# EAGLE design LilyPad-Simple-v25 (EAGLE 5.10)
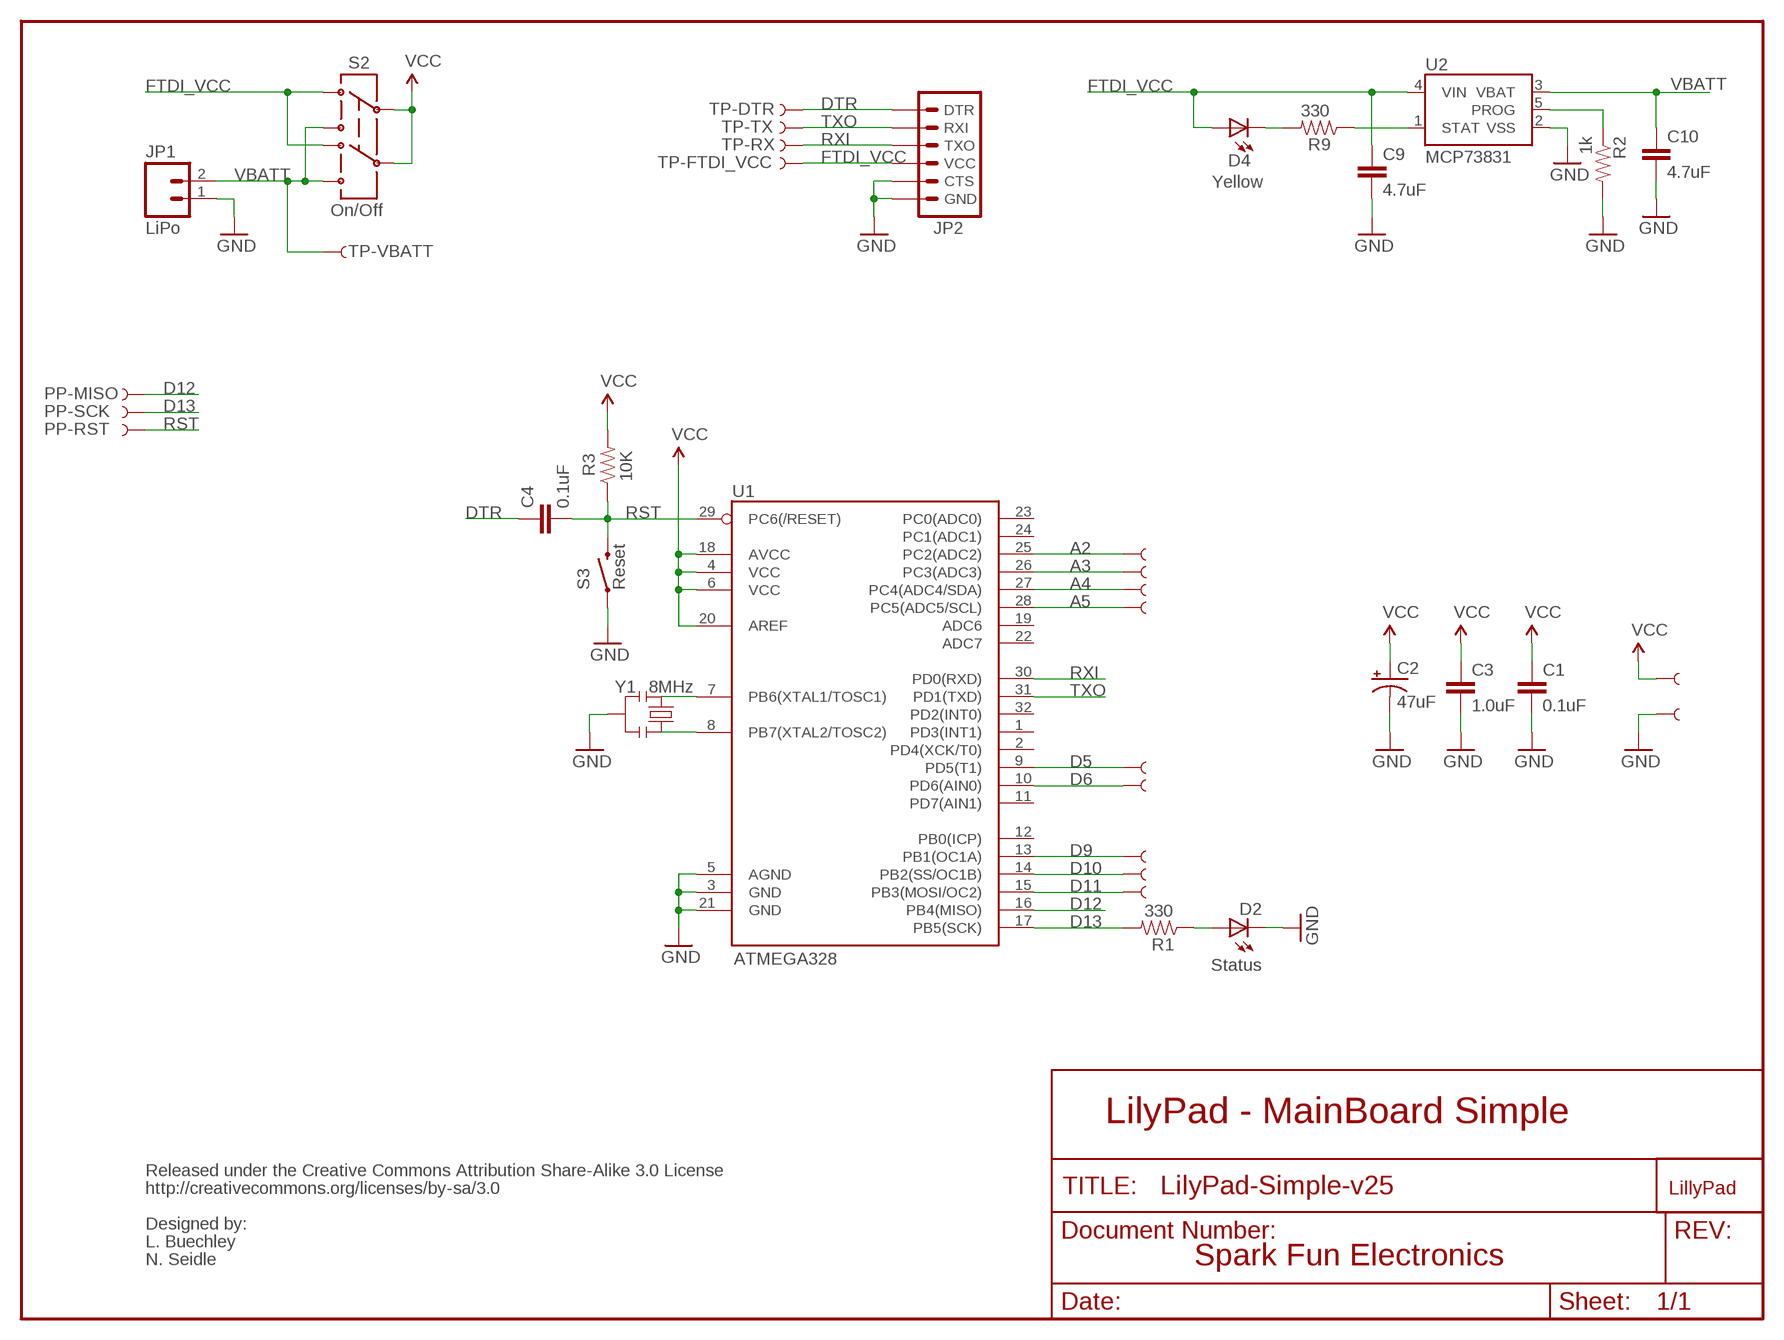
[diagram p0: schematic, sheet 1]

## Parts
A2/16  SEWTAP9  [PETAL-LONG-1-2SIDE]
A3/17  SEWTAP9  [PETAL-LONG-1-2SIDE]
A4/18  SEWTAP9  [PETAL-LONG-1-2SIDE]
A5/19  SEWTAP9  [PETAL-LONG-1-2SIDE]
C1  0.1uF  CAP0402-CAP  [0402-CAP]
C2  47uF  CAP_POL3528  [EIA3528]
C3  1.0uF  CAP0402-CAP  [0402-CAP]
C4  0.1uF  CAP0402-CAP  [0402-CAP]
C9  4.7uF  CAP0402-CAP  [0402-CAP]
C10  4.7uF  CAP0402-CAP  [0402-CAP]
D2  Status  LED0603  [LED-0603]
D4  Yellow  LED0603  [LED-0603]
JP1  LiPo  M02-JST-2MM-SMT  [JST-2-SMD]
JP2  ARDUINO_SERIAL_PROGRAMSMD  [1X06-SMD]
PP-MISO  TEST-POINT3X5  [PAD.03X.05]
PP-RST  TEST-POINT3X5  [PAD.03X.05]
PP-SCK  TEST-POINT3X5  [PAD.03X.05]
R1  330  RESISTOR0402-RES  [0402-RES]
R2  1k  RESISTOR0402-RES  [0402-RES]
R3  10K  RESISTOR0402-RES  [0402-RES]
R9  330  RESISTOR0402-RES  [0402-RES]
S2  On/Off  AYZ0202  [AYZ0202]
S3  Reset  SWITCH-MOMENTARY-2SMD  [TACTILE_SWITCH_SMD]
TP-DTR  TEST-POINT3X5  [PAD.03X.05]
TP-FTDI_VCC  TEST-POINT3X5  [PAD.03X.05]
TP-RX  TEST-POINT3X5  [PAD.03X.05]
TP-TX  TEST-POINT3X5  [PAD.03X.05]
TP-VBATT  TEST-POINT3X5  [PAD.03X.05]
U1  ATMEGA328  ATMEGA168  [TQFP32-08]
U2  MCP73831  [SOT23-5]
U$1  LOGO-LPLPA  [LOGO-LPA]
U$4  SEWTAP9  [PETAL-LONG-1-2SIDE]
U$35  SEWTAP9  [PETAL-LONG-1-2SIDE]
U$37  SEWTAP9  [PETAL-LONG-1-2SIDE]
U$39  SEWTAP9  [PETAL-LONG-1-2SIDE]
U$41  SEWTAP9  [PETAL-LONG-1-2SIDE]
U$43  SEWTAP9  [PETAL-LONG-1-2SIDE]
U$45  SEWTAP9  [PETAL-LONG-1-2SIDE]
Y1  8MHz  RESONATORSMD  [RESONATOR-SMD]

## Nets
A2: A2/16.1 U1.25(PC2(ADC2))
A3: A3/17.1 U1.26(PC3(ADC3))
A4: A4/18.1 U1.27(PC4(ADC4/SDA))
A5: A5/19.1 U1.28(PC5(ADC5/SCL))
D5: U1.9(PD5(T1)) U$41.1
D6: U1.10(PD6(AIN0)) U$35.1
D9: U1.13(PB1(OC1A)) U$37.1
D10: U1.14(PB2(SS/OC1B)) U$39.1
D11: U1.15(PB3(MOSI/OC2)) U$4.1
D12: PP-MISO.P$1 U1.16(PB4(MISO))
D13: PP-SCK.P$1 R1.2 U1.17(PB5(SCK))
DTR: C4.1 JP2.1(DTR) TP-DTR.P$1
FTDI_VCC: C9.1 D4.A JP2.4(VCC) S2.3 S2.6 TP-FTDI_VCC.P$1 U2.4(VIN)
GND [VCC]: C1.2 C2.C(-) C3.2 C9.2 C10.2 D2.C JP1.1 JP2.5(CTS) JP2.6(GND) R2.2 S3.1 U1.3(GND) U1.5(AGND) U1.21(GND) U2.2(VSS) U$43.1 Y1.2
N$1: U1.7(PB6(XTAL1/TOSC1)) Y1.1
N$2: D2.A R1.1
N$3: U1.8(PB7(XTAL2/TOSC2)) Y1.3
N$8: D4.C R9.2
PROG: R2.1 U2.5(PROG)
RST: C4.2 PP-RST.P$1 R3.1 S3.3 U1.29(PC6(/RESET))
RXI: JP2.3(TXO) TP-RX.P$1 U1.30(PD0(RXD))
STAT: R9.1 U2.1(STAT)
TXO: JP2.2(RXI) TP-TX.P$1 U1.31(PD1(TXD))
VBATT: C10.1 JP1.2 S2.1 S2.4 TP-VBATT.P$1 U2.3(VBAT)
VCC [VCC]: C1.1 C2.A(+) C3.1 R3.2 S2.2 S2.5 U1.4(VCC) U1.6(VCC) U1.18(AVCC) U1.20(AREF) U$45.1
Unconnected: U1.1(PD3(INT1)) U1.2(PD4(XCK/T0)) U1.11(PD7(AIN1)) U1.12(PB0(ICP)) U1.19(ADC6) U1.22(ADC7) U1.23(PC0(ADC0)) U1.24(PC1(ADC1)) U1.32(PD2(INT0))

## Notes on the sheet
- LilyPad - MainBoard Simple
- Released under the Creative Commons Attribution Share-Alike 3.0 License
- http://creativecommons.org/licenses/by-sa/3.0
- Designed by:
- L. Buechley
- N. Seidle | Spark Fun Electronics

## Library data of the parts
A2/16 A3/17 A4/18 A5/19 U$4 U$35 U$37 U$39 U$41 U$43 U$45 = LilyPad-Wearables:SEWTAP
C1 C3 C4 C9 C10 = SparkFun:CAP: Capacitor
C2 = SparkFun:CAP_POL: Capacitor Polarized
D2 D4 = SparkFun:LED: LEDs
JP1 = SparkFun:M02: Header 2
JP2 = SparkFun:ARDUINO_SERIAL_PROGRAM
PP-MISO PP-RST PP-SCK TP-DTR TP-FTDI_VCC TP-RX TP-TX TP-VBATT = SparkFun:TEST-POINT
R1-R3 R9 = SparkFun:RESISTOR: Resistor
S2 = SparkFun:AYZ0202: SPDT Slide Switch Simple SMD single-pull double-throw slide switch. Good for less than 350mA power switch, switching UARTs between devices, etc. Spark Fun Electronics SKU : COM-00597
S3 = SparkFun:SWITCH-MOMENTARY-2
U1 = SparkFun:ATMEGA168
U2 = SparkFun:MCP73831: Microchip's MCP73831 Miniature single cell, fully integrated Li-Ion, Li-polymer charge management controller http://ww1.microchip.com/downloads/en/DeviceDoc/21984a.pdf
U$1 = LilyPad-Wearables:LOGO-LP
Y1 = SparkFun:RESONATOR: Resonator Small SMD resonator. This is the itty bitty 10/20MHz resonators with built in caps. CSTCE10M0G55 and CSTCE20M0V53. Footprint has been reviewed closely but hasn't been tested yet.

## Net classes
0 Default: width 0.203 mm
1 VCC: width 0.254 mm

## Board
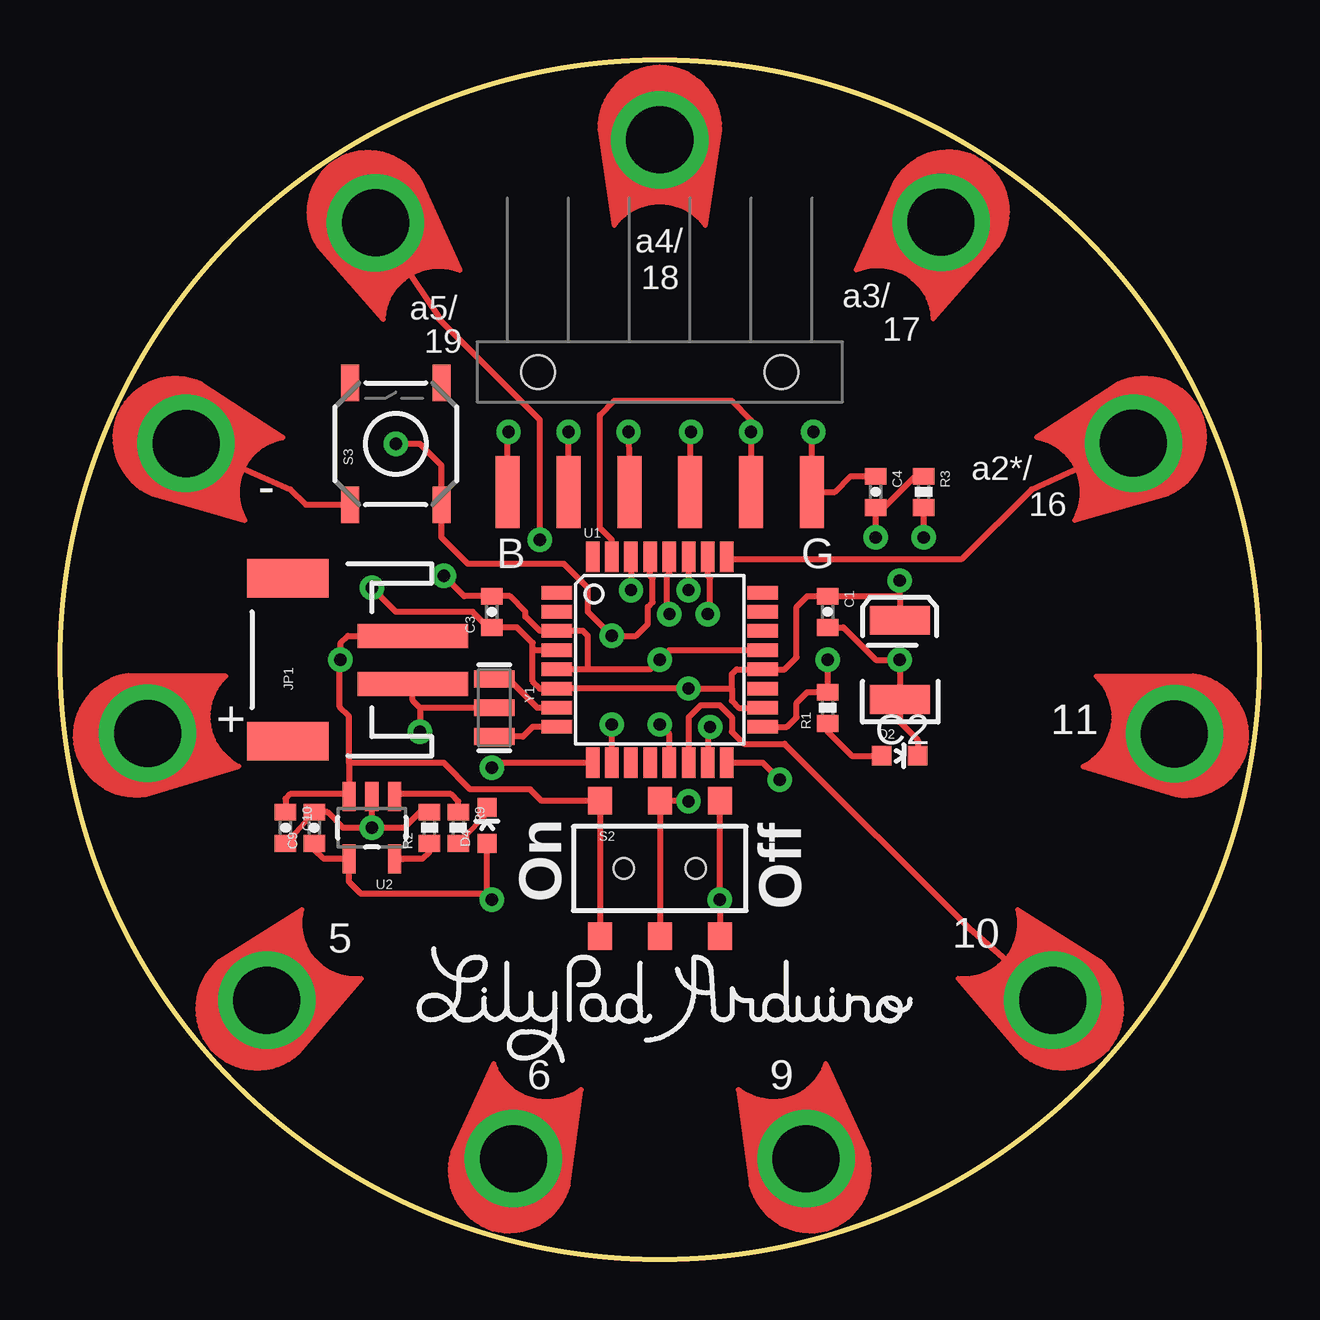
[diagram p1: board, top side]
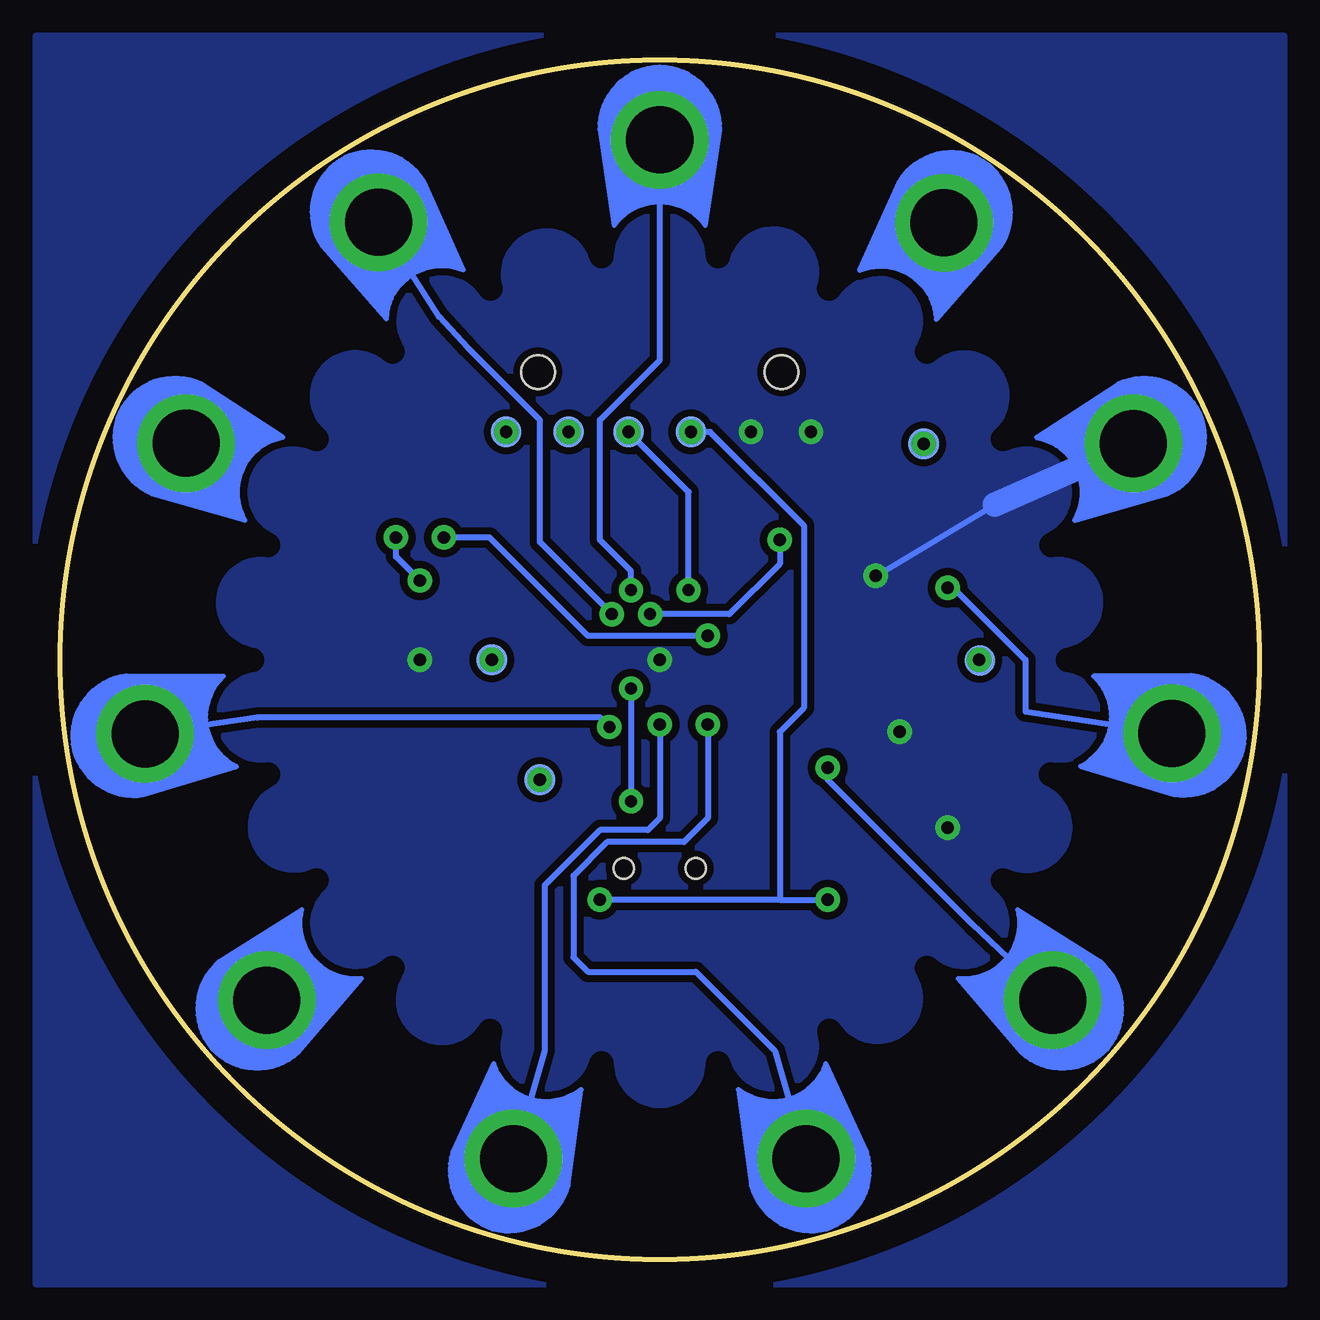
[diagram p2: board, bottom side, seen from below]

Size 50 x 50 mm. Coordinates in mm from the lower left corner, seen from the top.
Outline: circle at 25,25 radius 25
Copper layers (1*16): Top 0.035mm / dielectric 1.5mm / Bottom 0.035mm
Design rules "SparkFun": minimum track width 8mil, minimum drill 20mil, track to track 8mil, track to pad 8mil, pad to pad 8mil, via to via 8mil, smd to smd 8mil, copper to edge 8mil, drill to drill 8mil, minimum pad ring 12mil, minimum via ring 10mil, stop-mask expansion 4mil, vias tented up to drill 20mil, thermal gap 10mil
bRestrict: area 2.4,2.4 to 47.6,47.6; area 21,42.8 to 23.5,44; area 31.6,41.3 to 34.4,43; area 36.3,38.4 to 38.9,40.7; area 40,34.1 to 42,36.9; area 42.2,29.2 to 43.6,31.8; area 42.8,23.9 to 44,26.2; area 42.2,18.2 to 43.7,20.9; area 36.3,9.4 to 39,11.7; area 31.7,7 to 34.5,8.7; area 26.5,6 to 28.9,7.3; area 21.1,6 to 23.6,7.3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; 22 lines

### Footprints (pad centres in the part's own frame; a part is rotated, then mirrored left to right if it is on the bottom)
PETAL-LONG-1-2SIDE = drill 2.794 pad 4.064 round: 1 0.03,0
0402-CAP = smd 0.7 x 0.9: 1 -0.65,0; 2 0.65,0
EIA3528 = smd 1.2 x 2.5: A 1.65,0; C -1.65,0
LED-0603 = smd 0.8 x 0.8: A 0,-0.75; C 0,0.75
JST-2-SMD = smd 1 x 4.6: 1 -1,-3.7; 2 1,-3.7 | smd 1.6 x 3.4: NC1 -3.4,1.5; NC2 3.4,1.5
1X06-SMD = smd 1 x 3: 1 -6.35,5; 2 -3.81,5; 3 -1.27,5; 4 1.27,5; 5 3.81,5; 6 6.35,5 | hole 1.4: -5.08,0; 5.08,0
PAD.03X.05 = smd 1.27 x 1.27: P$1 0,0
0402-RES = smd 0.7 x 0.9: 1 -0.65,0; 2 0.65,0
AYZ0202 = smd 1 x 1.15: 1 -2.5,2.825; 2 0,2.825; 3 2.5,2.825; 4 -2.5,-2.825; 5 0,-2.825; 6 2.5,-2.825 | hole 0.85: 1.5,0; -1.5,0
TACTILE_SWITCH_SMD = smd 1.524 x 0.762: 1 -2.54,1.905; 2 2.54,1.905; 3 -2.54,-1.905; 4 2.54,-1.905
TQFP32-08 = smd 1.27 x 0.559: 1 -4.293,2.8; 2 -4.293,2; 3 -4.293,1.2; 4 -4.293,0.4; 5 -4.293,-0.4; 6 -4.293,-1.2; 7 -4.293,-2; 8 -4.293,-2.8; 17 4.293,-2.8; 18 4.293,-2; 19 4.293,-1.2; 20 4.293,-0.4; 21 4.293,0.4; 22 4.293,1.2; 23 4.293,2; 24 4.293,2.8 | smd 0.559 x 1.27: 9 -2.8,-4.293; 10 -2,-4.293; 11 -1.2,-4.293; 12 -0.4,-4.293; 13 0.4,-4.293; 14 1.2,-4.293; 15 2,-4.293; 16 2.8,-4.293; 25 2.8,4.293; 26 2,4.293; 27 1.2,4.293; 28 0.4,4.293; 29 -0.4,4.293; 30 -1.2,4.293; 31 -2,4.293; 32 -2.8,4.293
SOT23-5 = smd 0.55 x 1.2: 1 -0.95,-1.3; 2 0,-1.3; 3 0.95,-1.3; 4 0.95,1.3; 5 -0.95,1.3
RESONATOR-SMD = smd 0.7 x 1.7: 1 -1.2,0; 2 0,0; 3 1.2,0

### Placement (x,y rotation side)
A2/16  44.77,34.04 204.5 top
A3/17  36.74,43.26 237.3 top
A4/18  25,46.7 270 top
A5/19  13.13,43.24 302.7 top
C1  32,27 270 top
C2  35,25 90 top
C3  18,27 90 top
C4  34,32 270 top
C9  10.6,18 90 top
C10  9.4,18 270 top
D2  35,21 270 top
D4  17.8,18.1 0 top
JP1  11,25 90 top
JP2  25,37 180 top
PP-MISO  30,20 0 bottom
PP-RST  14,34 0 bottom
PP-SCK  32,25 0 bottom
R1  32,23 90 top
R2  15.4,18 90 top
R3  36,32 270 top
R9  16.6,18 270 top
S2  25,16.3 0 top
S3  14,34 90 top
TP-DTR  31.4,34.5 0 bottom
TP-FTDI_VCC  23.7,34.5 0 bottom
TP-RX  26.3,34.5 0 bottom
TP-TX  28.8,34.5 90 bottom
TP-VBATT  11.66,24.97 0 bottom
U1  25,25 0 top
U2  13,18 180 top
U$1  25,11 0 top
U$4  46.48,21.91 171.8 top
U$35  18.89,4.17 73.7 top
U$37  31.11,4.17 106.3 top
U$39  41.4,10.79 139.1 top
U$41  8.6,10.79 40.9 top
U$43  5.23,34.03 335.5 top
U$45  3.62,21.92 8.2 top
Y1  18.1,23 270 top

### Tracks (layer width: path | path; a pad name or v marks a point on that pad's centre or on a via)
A2
  Top 0.254: A2/16.1 40.5,32.1 37.6,29.2 27.89,29.2 U1.25
A3  (via drill 0.51)
  Top 0.254: U1.26 27,28.5 27.1,28.4 27.1,27 v27,26.9
  Bottom 0.254: A3/17.1 34.2,39.3 33,38 30,35 30,29.9 v27,26.9
A4  (via drill 0.51)
  Top 0.254: U1.27 v26.2,27.9
  Bottom 0.254: v26.2,27.9 26.2,28.7 27.5,30 27.5,35 25,37.5 A4/18.1
A5  (via drill 0.51)
  Top 0.254: A5/19.1 15.8,39.3 15.8,39.2 20,35 v20,30 | U1.28 25.4,28.6 25.3,28.5 25.3,27 v25.4,26.9
  Bottom 0.254: v20,30 20,29 22.1,26.9 v25.4,26.9
D5  (via drill 0.51)
  Top 0.254: U1.9 18.21,20.71 v18,20.5
  Bottom 0.254: U$41.1 12,14 18,20 v18,20.5
D6  (via drill 0.51)
  Top 0.254: U1.10 v23,22.3
  Bottom 0.254: v23,22.3 23,18.4 24,17.4 27.2,17.4 28.6,16 28.6,12.6 28,12 23.5,12 20.2,8.7 U$35.1
D9  (via drill 0.51)
  Top 0.254: U1.13 25.4,21.9 v25,22.3
  Bottom 0.254: v25,22.3 25,18.4 25.5,17.9 27.5,17.9 29.8,15.6 29.8,8.7 U$37.1
D10
  Top 0.254: U$39.1 37.9,13.8 30.2,21.5 28.5,21.5 28,22 28,22.6 27.5,23.1 26.7,23.1 26.2,22.6 U1.14
D11  (via drill 0.51)
  Top 0.254: U1.15 27,22.1 v27.1,22.2
  Bottom 0.254: v27.1,22.2 27.5,22.6 41.76,22.6 41.76,22.59 U$4.1
D12  (via drill 0.51)
  Top 0.254: U1.16 29.29,20.71 PP-MISO.P$1
  other vias: 30,20
D13  (via drill 0.51)
  Top 0.254: PP-SCK.P$1 R1.2 31.15,23.65 30.7,23.2 30.7,22.6 30.3,22.2 U1.17
  other vias: 32,25
DTR  (via drill 0.51)
  Top 0.254: TP-DTR.P$1 31.35,34.45 JP2.1 32.3,32 32.95,32.65 C4.1
  other vias: 31.4,34.5
FTDI_VCC  (via drill 0.51)
  Top 0.254: S2.3 v27.5,15 S2.6 | U2.4 12.05,15.75 12.55,15.25 17.75,15.25 v18,15 17.8,15.2 D4.A | C9.1 10.6,17.1 11,16.7 U2.4 | U2.4 | TP-FTDI_VCC.P$1 JP2.4
  Bottom 0.254: 20,15 v18,15 | 20,15 v27.5,15 | 20,15 20,22 19,23 19,30.6 22.9,34.5 TP-FTDI_VCC.P$1
  other vias: 23.7,34.5
GND  (via drill 0.51)
  Top 0.203: C9.2 C10.2
  Top 0.254: U1.21 25.4,25.4 v25,25 24.6,24.6 22,24.6 | 22,24.6 U1.5 | 22,24.6 22,26 21.8,26.2 U1.3 20,26.2 19.4,26.8 19.4,27 18.75,27.65 C3.2 16.85,27.65 v16,28.5 | U$43.1 9.6,32.1 10.24,31.46 S3.1 | v13,18 U2.2 | C1.2 32.65,26.35 34,25 v35,25 C2.C 35,22.4 35.75,21.65 D2.C | v13,18 14.35,18 15,18.65 R2.2 | C9.2 11.15,18.65 11.8,18 v13,18 | Y1.2 15,23 | JP1.1 14.7,23.3 15,23 | 15,23 v15,22 | JP2.6 18.65,34.45 v18.7,34.5 | JP2.5 v21.19,34.49 v21.2,34.5
  Bottom 0.254: v16,28.5 11.03,31.46
  Bottom 1.016: 11.03,31.46 U$43.1
  pour Bottom (isolate 0.305): -1,51 51,51 51,-1 -1,-1
N$1
  Top 0.254: U1.7 19.9,23 18.7,24.2 Y1.1
N$2
  Top 0.254: R1.1 32,22 33,21 D2.A
N$3
  Top 0.254: U1.8 19.7,22.2 19.3,21.8 Y1.3
N$8
  Top 0.203: R9.2 17.5,18.3 17.8,18.6 D4.C
PROG
  Top 0.254: U2.5 14.35,16.7 | R2.1 15.4,17 15.1,16.7 U2.5 | U2.5
RST  (via drill 0.51)
  Top 0.254: v34,30.1 C4.2 34.35,31.35 35.65,32.65 R3.1 | U1.29 24.6,28.5 24.7,28.4 24.7,27.4 24.5,27.2 24.5,26.5 24,26 v23,26 22,27 22,28 21,29 17,29 15.9,30.09 S3.3 15.9,33.09 15,34 PP-RST.P$1
  Bottom 0.254: v23,26 28,26 32.1,30.1 v34,30.1
  other vias: 14,34
RXI  (via drill 0.51)
  Top 0.254: U1.30 v23.8,27.9 | JP2.3 26.27,34.47 TP-RX.P$1
  Bottom 0.254: v23.8,27.9 23.8,32 TP-RX.P$1
  other vias: 26.3,34.5
STAT
  Top 0.254: R9.1 16.6,19.1 16.3,19.4 14.05,19.4 U2.1
TXO  (via drill 0.51)
  Top 0.254: U1.31 23,30 22.5,30.5 22.5,35.2 23.1,35.8 28,35.8 28.8,35 TP-TX.P$1 JP2.2
  other vias: 28.8,34.5
VBATT  (via drill 0.51)
  Top 0.254: S2.4 S2.1 20.07,19.12 19.6,19.6 17.1,19.6 16,20.7 12.05,20.7 | JP1.2 12,26 11.7,25.7 | C10.1 9.4,19.2 9.6,19.4 11.95,19.4 U2.3 12.05,20.7 | 12.05,20.7 12.05,22.65 11.66,23.04 TP-VBATT.P$1 v11.69,25 | v11.69,25 v11.7,25.01 11.7,25.7 | 11.7,25.7 11.69,25.69 v11.69,25
  Bottom 0.254: 11.66,25 v11.69,25 TP-VBATT.P$1
VCC  (via drill 0.51)
  Top 0.254: 19.7,25.5 19.7,24.1 20,23.8 U1.6 v26.2,23.8 28,23.8 | 19.7,25.5 19.7,25.7 19.05,26.35 C3.1 17.85,26.35 17.2,27 14,27 v13,28 | U1.4 19.8,25.4 19.7,25.5 | S2.5 S2.2 26.18,19.12 v26.2,19.1 | 35,27.6 C2.A | 35,27.6 v35,28.3 | 35,27.6 34.95,27.65 C1.1 31.15,27.65 30.7,27.2 30.7,25.1 30.2,24.6 U1.20 28.2,24.6 28,24.4 28,23.8 | v36,30.1 R3.2 | U1.18 28.3,23 28,23.3 28,23.8
  Bottom 0.254: v26.2,23.8 v26.2,19.1 | v36,30.1 36,29.3 v35,28.3 | v13,28 12.76,28 9.76,25 9.76,22.84 U$45.1

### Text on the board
tPlace: a4/ | 18 | a3/ | a5/ | 19 | 17 | a2*/ | - | 16 | B | G | + | 11 | On | Off | 5 | 10 | 6 | 9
